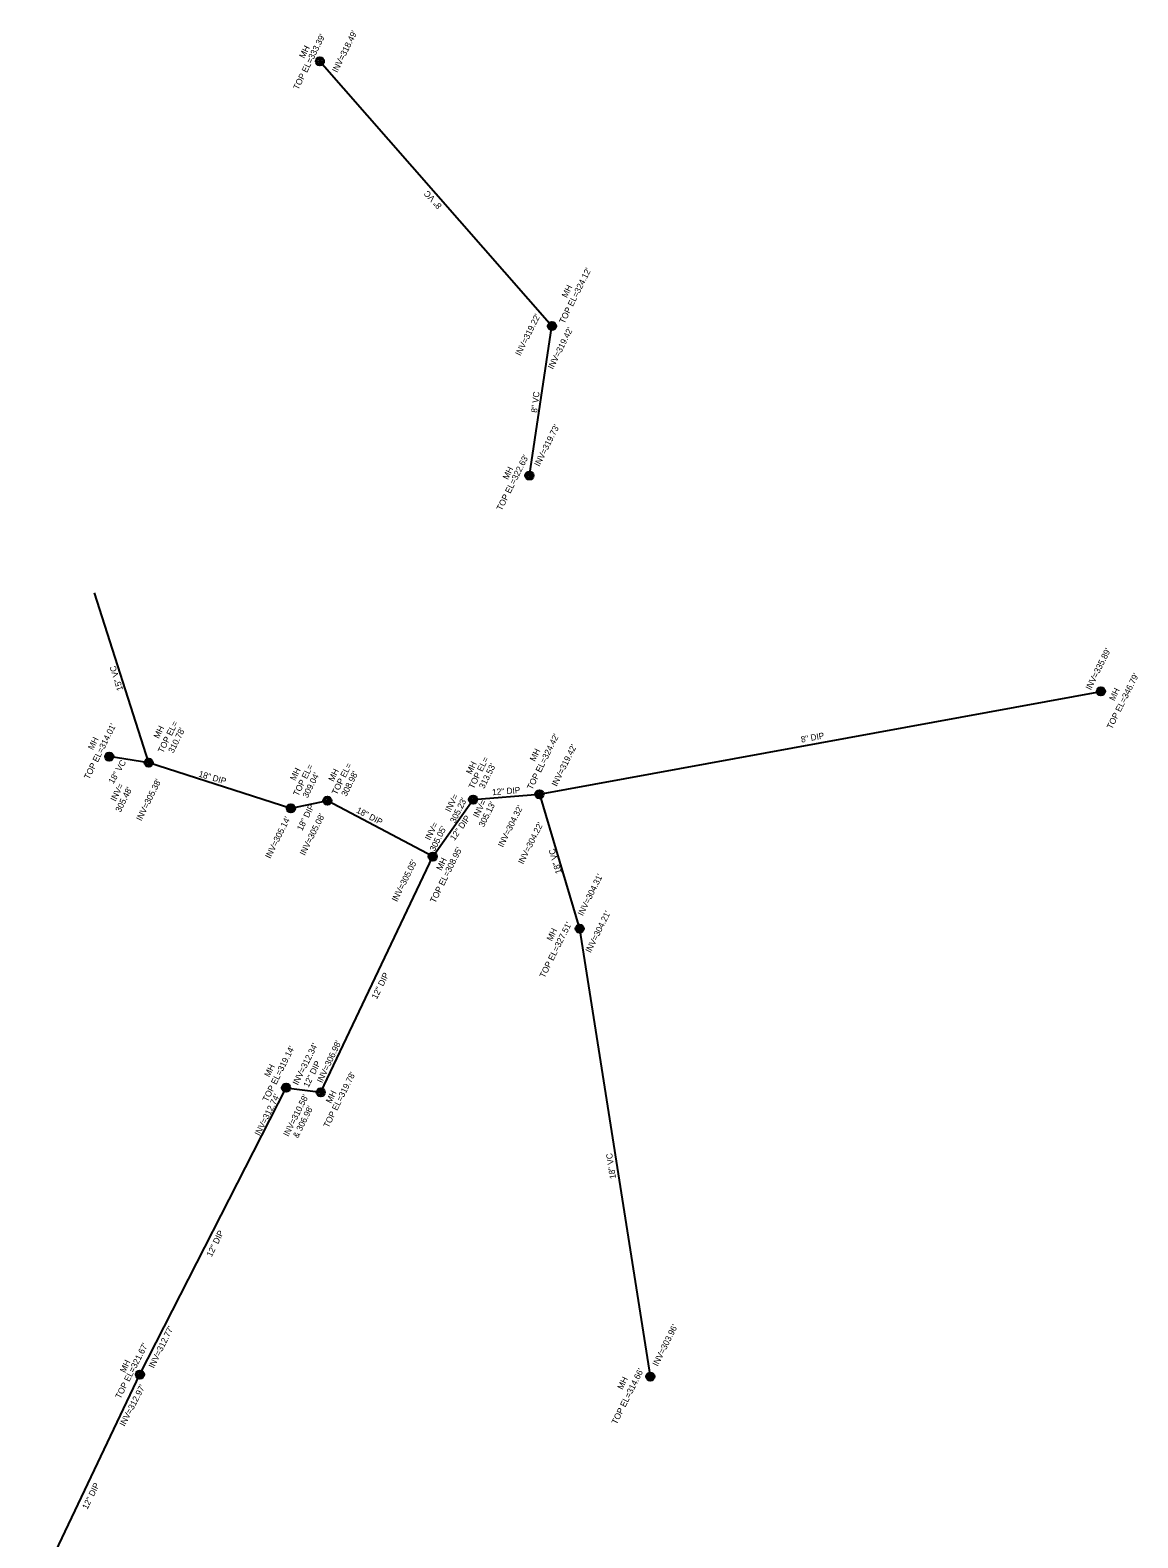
# Model space of a CAD drawing. Extents: x 1975698 to 1978521, y 778259 to 782969.
# Drawn here: x 1977803 to 1978521, y 781991 to 782969 of the extents above; entities that cross this region are included whole.
import ezdxf

# ---------------------------------------------------------------- set-up
doc = ezdxf.new("R2010")
doc.units = 0
for name, color, linetype in [('Old_Level_11', 7, 'Continuous'), ('Old_Level_5', 7, 'Continuous'), ('Prop Horizontal Alignment', 7, 'Continuous'), ('Prop Horizontal Alignment Station Label', 7, 'Continuous'), ('Prop WCC CELL', 7, 'Continuous')]:
    doc.layers.add(name, color=color, linetype=linetype)

# ---------------------------------------------------------------- blocks, each defined once
blk = doc.blocks.new('EXIST UTILITIES SANITARY SEWER MANHOLE')
at = {"layer": 'Prop Horizontal Alignment'}
blk.add_lwpolyline([(0, 0.034), (0, -0.034), (0, 0), (0.034, 0), (-0.034, 0)], dxfattribs=at)
for radius in [0.0539, 0.0342]:
    blk.add_circle((0, 0), radius, dxfattribs=at)

msp = doc.modelspace()

# ---------------------------------------------------------------- linework, layer by layer
at = {"layer": 'Old_Level_5'}
for p, q in [((1977995.22, 782469.23), (1977971.55, 782464.22)), ((1978063.56, 782432.99), (1977995.22, 782469.23))]:
    msp.add_line(p, q, dxfattribs=at)
at = {"layer": 'Prop Horizontal Alignment Station Label'}
for p, q in [((1978140.84, 782776.96), (1977990.33, 782948.63)), ((1978126.25, 782680.08), (1978140.84, 782776.96)), ((1977879.36, 782493.87), (1977844.2, 782603.91)), ((1978132.74, 782473.42), (1978496.72, 782540.1)), ((1977879.36, 782493.87), (1977853.79, 782497.8)), ((1977971.55, 782464.22), (1977879.36, 782493.87)), ((1978089.73, 782469.94), (1978132.74, 782473.42)), ((1978132.74, 782473.42), (1978158.78, 782386.22)), ((1978063.56, 782432.99), (1978089.73, 782469.94)), ((1977990.94, 782280.13), (1978063.56, 782432.99)), ((1978158.78, 782386.22), (1978204.59, 782095.84)), ((1977873.64, 782097.11), (1977968.44, 782283.07)), ((1977968.44, 782283.07), (1977990.94, 782280.13)), ((1977802.51, 781947.79), (1977873.64, 782097.11))]:
    msp.add_line(p, q, dxfattribs=at)

# ---------------------------------------------------------------- block references
at = {"layer": 'Prop Horizontal Alignment', "xscale": 50, "yscale": 50}
for p in [(1977990.33, 782948.63), (1978140.84, 782776.96), (1978126.25, 782680.08), (1978496.72, 782540.1), (1977853.79, 782497.8), (1977879.36, 782493.87), (1977995.22, 782469.23), (1978089.73, 782469.94), (1978132.74, 782473.42), (1977971.55, 782464.22), (1978063.56, 782432.99), (1978158.78, 782386.22), (1977968.44, 782283.07), (1977990.94, 782280.13), (1977873.64, 782097.11), (1978204.59, 782095.84)]:
    msp.add_blockref('EXIST UTILITIES SANITARY SEWER MANHOLE', p, dxfattribs=at)

# ---------------------------------------------------------------- texts
at = {"layer": 'Old_Level_11'}
for s, rotation, p in [('8" VC', 132.70499, (1978069.69, 782855.13)), ('8" VC', 83.39688, (1978131.21, 782720.58)), ('15" VC', 107.69822, (1977862.88, 782541.2)), ('8" DIP', 10.38199, (1978302.62, 782506.87)), ('18" VC', 59.57337, (1977856.42, 782479.78)), ('18" DIP', 343.80608, (1977911.41, 782484.88)), ('12" DIP', 4.61921, (1978102.22, 782472.74)), ('18" DIP', 63.66842, (1977978.85, 782449.36)), ('18" DIP', 332.23738, (1978013.56, 782461.76)), ('12" DIP', 54.69563, (1978077.61, 782443)), ('18" VC', 106.62741, (1978147.23, 782422.49)), ('12" DIP', 63.66842, (1978027.25, 782340.18)), ('12" DIP', 63.66842, (1977982.96, 782282.95)), ('18" VC', 98.96407, (1978182.4, 782224.36)), ('12" DIP', 63.66842, (1977920.16, 782173.03)), ('12" DIP', 63.66842, (1977839.58, 782009.36))]:
    msp.add_text(s, height=4, rotation=rotation, dxfattribs=at).set_placement(p)
at = {"layer": 'Prop WCC CELL'}
for s, rotation, p in [("TOP EL=333.39'", 63.49181, (1977976.37, 782929.77)), ("INV=318.49'", 63.49181, (1978001.61, 782940.98)), ('MH', 63.49181, (1977980.26, 782950.17)), ("TOP EL=324.12'", 63.49181, (1978148.82, 782778.14)), ('MH', 63.49181, (1978150.51, 782794.96)), ("INV=319.22'", 63.49181, (1978120.35, 782757.3)), ("INV=319.42'", 63.49181, (1978141.5, 782748.61)), ("INV=319.73'", 63.49181, (1978132.7, 782685.57)), ("TOP EL=322.63'", 63.49181, (1978108.22, 782656.9)), ('MH', 63.49181, (1978112.23, 782677.07)), ("INV=335.89'", 63.49181, (1978490.19, 782540.57)), ("TOP EL=346.79'", 63.49181, (1978503.88, 782515.26)), ('MH', 63.49181, (1978505.43, 782533.62)), ("TOP EL=314.01'", 63.49181, (1977840.74, 782482.65)), ('TOP EL=', 63.49181, (1977888.64, 782499.76)), ('MH', 63.49181, (1977843.27, 782501.78)), ('MH', 63.49181, (1977885.89, 782509.15)), ("310.78'", 63.49181, (1977895.33, 782499.73)), ("TOP EL=324.42'", 63.49181, (1978127.98, 782475.97)), ('MH', 63.48983, (1978129.76, 782494.32)), ("INV=319.42'", 63.49181, (1978143.9, 782478.13)), ('MH', 63.49181, (1977974.33, 782481.84)), ('TOP EL=', 63.49181, (1977976.33, 782471.82)), ('TOP EL=', 63.49181, (1978001.37, 782472.64)), ('MH', 63.48983, (1978088.46, 782485.97)), ('TOP EL=', 63.48983, (1978090.05, 782476.5)), ("313.53'", 63.48983, (1978096.82, 782476.61)), ("INV=305.38'", 63.49181, (1977874.56, 782455.75)), ("309.04'", 63.49181, (1977982.44, 782470.64)), ('MH', 63.49181, (1977999.17, 782481.26)), ("308.98'", 63.49181, (1978007.55, 782471.6)), ('INV=', 63.49181, (1977857.92, 782468.4)), ("305.48'", 63.49181, (1977861.08, 782461.3)), ('INV=', 63.48983, (1978074.9, 782461.45)), ("305.23'", 63.48983, (1978078.06, 782454.34)), ("INV=305.08'", 63.49181, (1977980.58, 782433.32)), ('INV=', 63.48983, (1978092.99, 782457.85)), ("305.13'", 63.48983, (1978096.66, 782451.76)), ("INV=304.32'", 63.49181, (1978109.08, 782438.64)), ("INV=305.14'", 63.49181, (1977958.23, 782431.34)), ('INV=', 63.48983, (1978061.75, 782443.21)), ("305.05'", 63.48983, (1978064.84, 782435.97)), ("INV=304.22'", 63.49181, (1978122.14, 782427.64)), ("TOP EL=308.95'", 63.48983, (1978065.11, 782402.51)), ('MH', 63.48983, (1978069.16, 782423.58)), ("INV=305.05'", 63.48983, (1978040.36, 782403.35)), ("INV=304.31'", 63.49181, (1978160.82, 782394.16)), ("INV=304.21'", 63.49181, (1978165.88, 782370.22)), ("TOP EL=327.51'", 63.49181, (1978136.09, 782353.91)), ('MH', 63.49181, (1978140.69, 782377.8)), ("TOP EL=319.14'", 63.49178, (1977956.45, 782273.59)), ("INV=312.34'", 63.49178, (1977976.03, 782284.43)), ("INV=306.98'", 64.6252, (1977991.78, 782285.89)), ('MH', 63.49178, (1977957.61, 782289.63)), ("TOP EL=319.78'", 63.49178, (1977995.97, 782256.74)), ("INV=312.74'", 63.49178, (1977951.34, 782251.53)), ("INV=310.58' ", 63.49178, (1977969.95, 782251.09)), ('MH', 63.49178, (1977997.57, 782272.63)), ("& 306.98'", 63.49178, (1977976.16, 782250.1)), ("INV=312.77'", 63.87516, (1977882.69, 782100.84)), ("INV=303.96'", 63.49181, (1978209.37, 782102.09)), ("TOP EL=321.67'", 62.8836, (1977861.04, 782081.03)), ('MH', 64.45611, (1977864.09, 782097.94)), ("TOP EL=314.66'", 63.49181, (1978182.79, 782064.42)), ("INV=312.97'", 62.60987, (1977863.74, 782063.15)), ('MH', 63.49181, (1978186.52, 782087.01))]:
    msp.add_text(s, height=4, rotation=rotation, dxfattribs=at).set_placement(p)

doc.saveas('drawing.dxf')
